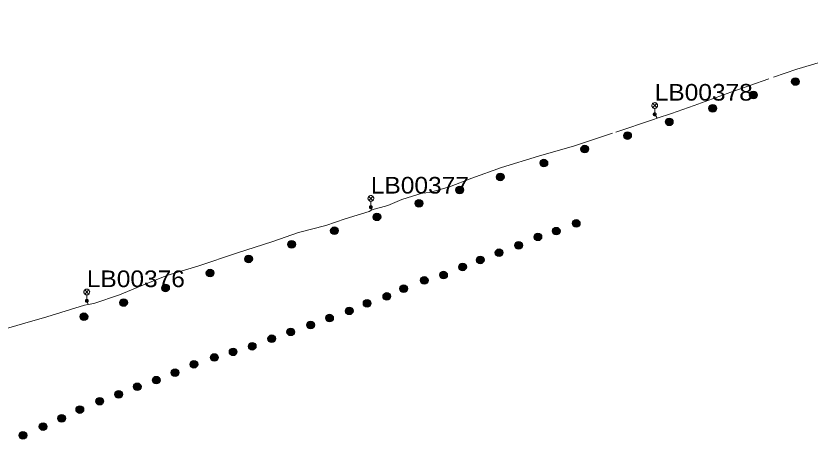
# Model space of a CAD drawing. Extents: x -688049 to -687261, y -973611 to -973038.
# Drawn here: x -687554.6 to -687451.2, y -973399.2 to -973344 of the extents above; entities that cross this region are included whole.
import ezdxf

# ---------------------------------------------------------------- set-up
doc = ezdxf.new("R2010")
doc.units = 0
doc.header["$LTSCALE"] = 0.87
doc.linetypes.add('LONG_DASH_SHORT_DASH', pattern=[9.9, 6, -1.2, 1.5, -1.2])
doc.layers.add('1', color=7, linetype='Continuous', lineweight=13)

msp = doc.modelspace()

# ---------------------------------------------------------------- hatches: boundary and pattern name
at = {"layer": '1'}
for points in [[(-687452.951, -973353.016, 1), (-687453.25, -973352.072, 1)], [(-687458.431, -973354.77, 1), (-687458.73, -973353.826, 1)], [(-687463.713, -973356.513, 1), (-687464.012, -973355.569, 1)], [(-687469.389, -973358.272, 1), (-687469.688, -973357.328, 1)], [(-687474.817, -973360.072, 1), (-687475.116, -973359.127, 1)], [(-687480.382, -973361.824, 1), (-687480.681, -973360.88, 1)], [(-687485.713, -973363.649, 1), (-687486.011, -973362.705, 1)], [(-687491.387, -973365.457, 1), (-687491.686, -973364.513, 1)], [(-687496.677, -973367.176, 1), (-687496.976, -973366.232, 1)], [(-687501.974, -973368.905, 1), (-687502.272, -973367.961, 1)], [(-687507.452, -973370.664, 1), (-687507.751, -973369.72, 1)], [(-687481.5, -973371.517, 1), (-687481.799, -973370.572, 1)], [(-687512.982, -973372.477, 1), (-687513.281, -973371.533, 1)], [(-687484.095, -973372.525, 1), (-687484.394, -973371.581, 1)], [(-687486.493, -973373.271, 1), (-687486.792, -973372.327, 1)], [(-687518.571, -973374.246, 1), (-687518.87, -973373.302, 1)], [(-687489.003, -973374.378, 1), (-687489.302, -973373.434, 1)], [(-687524.158, -973376.155, 1), (-687524.457, -973375.211, 1)], [(-687491.537, -973375.34, 1), (-687491.836, -973374.396, 1)], [(-687496.293, -973377.192, 1), (-687496.592, -973376.248, 1)], [(-687494, -973376.278, 1), (-687494.299, -973375.334, 1)], [(-687529.175, -973377.989, 1), (-687529.474, -973377.045, 1)], [(-687501.29, -973378.948, 1), (-687501.589, -973378.004, 1)], [(-687498.779, -973378.251, 1), (-687499.078, -973377.307, 1)], [(-687534.984, -973379.929, 1), (-687535.282, -973378.984, 1)], [(-687503.969, -973380.031, 1), (-687504.268, -973379.087, 1)], [(-687506.163, -973381.039, 1), (-687506.462, -973380.094, 1)], [(-687540.439, -973381.836, 1), (-687540.738, -973380.892, 1)], [(-687508.725, -973381.939, 1), (-687509.024, -973380.995, 1)], [(-687511.053, -973382.922, 1), (-687511.352, -973381.978, 1)], [(-687545.616, -973383.691, 1), (-687545.915, -973382.747, 1)], [(-687513.625, -973383.867, 1), (-687513.924, -973382.923, 1)], [(-687516.092, -973384.765, 1), (-687516.39, -973383.821, 1)], [(-687518.679, -973385.662, 1), (-687518.978, -973384.717, 1)], [(-687521.141, -973386.555, 1), (-687521.44, -973385.611, 1)], [(-687526.174, -973388.267, 1), (-687526.473, -973387.323, 1)], [(-687523.698, -973387.538, 1), (-687523.996, -973386.594, 1)], [(-687528.627, -973389.002, 1), (-687528.925, -973388.058, 1)], [(-687531.283, -973389.89, 1), (-687531.582, -973388.946, 1)], [(-687533.745, -973390.997, 1), (-687534.044, -973390.053, 1)], [(-687536.183, -973391.959, 1), (-687536.482, -973391.015, 1)], [(-687538.669, -973392.825, 1), (-687538.968, -973391.881, 1)], [(-687543.546, -973394.702, 1), (-687543.845, -973393.757, 1)], [(-687541.083, -973393.812, 1), (-687541.382, -973392.867, 1)], [(-687546.141, -973395.793, 1), (-687546.44, -973394.848, 1)], [(-687548.507, -973396.95, 1), (-687548.806, -973396.006, 1)], [(-687550.927, -973398.011, 1), (-687551.226, -973397.066, 1)], [(-687553.553, -973399.155, 1), (-687553.852, -973398.21, 1)]]:
    msp.add_hatch(color=256, dxfattribs=at).paths.add_polyline_path(points)

# ---------------------------------------------------------------- linework, layer by layer
for p, q in [((-687471.685, -973355.405), (-687471.155, -973355.935)), ((-687471.685, -973355.935), (-687471.155, -973355.405)), ((-687471.42, -973356.82), (-687471.42, -973356.045)), ((-687508.655, -973367.525), (-687508.125, -973368.055)), ((-687508.655, -973368.055), (-687508.125, -973367.525)), ((-687508.39, -973368.94), (-687508.39, -973368.165)), ((-687545.645, -973379.725), (-687545.115, -973380.255)), ((-687545.645, -973380.255), (-687545.115, -973379.725)), ((-687545.38, -973381.14), (-687545.38, -973380.365))]:
    msp.add_line(p, q, dxfattribs=at)
at = {"layer": '1', "linetype": 'LONG_DASH_SHORT_DASH'}
for p, q in [((-687471.1, -973357.3), (-687471.42, -973356.82)), ((-687508.25, -973369.29), (-687508.39, -973368.94)), ((-687545.21, -973381.61), (-687545.38, -973381.14))]:
    msp.add_line(p, q, dxfattribs=at)
for points in [[(-687471.1, -973357.3), (-687469.23, -973356.72), (-687466.28, -973355.69), (-687461.51, -973353.91), (-687455.96, -973351.99), (-687452.92, -973350.95), (-687449.84, -973350.04), (-687445.86, -973348.71), (-687442.97, -973347.78), (-687439.3, -973347.01), (-687435.78, -973345.76), (-687433.52, -973344.93), (-687431.83, -973344.36), (-687431.72, -973343.98)], [(-687508.25, -973369.29), (-687506.19, -973368.71), (-687504.36, -973367.92), (-687501.72, -973367.12), (-687500.76, -973367.03), (-687498.15, -973366.29), (-687495.25, -973365.16), (-687491.39, -973363.77), (-687486.58, -973362.27), (-687481.87, -973360.93), (-687476.48, -973359.14), (-687471.58, -973357.5), (-687471.1, -973357.3)], [(-687545.21, -973381.61), (-687544.47, -973381.51), (-687541.13, -973380.37), (-687538.32, -973379.2), (-687534.96, -973377.86), (-687530.79, -973376.56), (-687525.89, -973374.94), (-687521.16, -973373.42), (-687517.8, -973372.25), (-687514.26, -973371.3), (-687511.73, -973370.43), (-687508.63, -973369.51), (-687508.25, -973369.29)], [(-687556.57, -973384.95), (-687553.44, -973384.04), (-687550.57, -973383.25), (-687545.68, -973381.7), (-687545.21, -973381.61)]]:
    msp.add_lwpolyline(points, dxfattribs=at)
at = {"layer": '1'}
for points in [[(-687471.045, -973355.67), (-687471.051, -973355.605), (-687471.068, -973355.542), (-687471.095, -973355.482), (-687471.133, -973355.429), (-687471.179, -973355.383), (-687471.232, -973355.345), (-687471.292, -973355.318), (-687471.355, -973355.301), (-687471.42, -973355.295), (-687471.485, -973355.301), (-687471.548, -973355.318), (-687471.608, -973355.345), (-687471.661, -973355.383), (-687471.707, -973355.429), (-687471.745, -973355.482), (-687471.772, -973355.542), (-687471.789, -973355.605), (-687471.795, -973355.67), (-687471.789, -973355.735), (-687471.772, -973355.798), (-687471.745, -973355.857), (-687471.707, -973355.911), (-687471.661, -973355.957), (-687471.608, -973355.995), (-687471.548, -973356.022), (-687471.485, -973356.039), (-687471.42, -973356.045), (-687471.355, -973356.039), (-687471.292, -973356.022), (-687471.232, -973355.995), (-687471.179, -973355.957), (-687471.133, -973355.911), (-687471.095, -973355.857), (-687471.068, -973355.798), (-687471.051, -973355.735)], [(-687471.23, -973356.82), (-687471.233, -973356.787), (-687471.241, -973356.755), (-687471.255, -973356.725), (-687471.274, -973356.698), (-687471.298, -973356.674), (-687471.325, -973356.655), (-687471.355, -973356.641), (-687471.387, -973356.633), (-687471.42, -973356.63), (-687471.453, -973356.633), (-687471.485, -973356.641), (-687471.515, -973356.655), (-687471.542, -973356.674), (-687471.566, -973356.698), (-687471.585, -973356.725), (-687471.599, -973356.755), (-687471.607, -973356.787), (-687471.61, -973356.82), (-687471.607, -973356.853), (-687471.599, -973356.885), (-687471.585, -973356.915), (-687471.566, -973356.942), (-687471.542, -973356.966), (-687471.515, -973356.985), (-687471.485, -973356.999), (-687471.453, -973357.007), (-687471.42, -973357.01), (-687471.387, -973357.007), (-687471.355, -973356.999), (-687471.325, -973356.985), (-687471.298, -973356.966), (-687471.274, -973356.942), (-687471.255, -973356.915), (-687471.241, -973356.885), (-687471.233, -973356.853)], [(-687471.37, -973356.82), (-687471.371, -973356.811), (-687471.373, -973356.803), (-687471.377, -973356.795), (-687471.382, -973356.788), (-687471.388, -973356.782), (-687471.395, -973356.777), (-687471.403, -973356.773), (-687471.411, -973356.771), (-687471.42, -973356.77), (-687471.429, -973356.771), (-687471.437, -973356.773), (-687471.445, -973356.777), (-687471.452, -973356.782), (-687471.458, -973356.788), (-687471.463, -973356.795), (-687471.467, -973356.803), (-687471.469, -973356.811), (-687471.47, -973356.82), (-687471.469, -973356.829), (-687471.467, -973356.837), (-687471.463, -973356.845), (-687471.458, -973356.852), (-687471.452, -973356.858), (-687471.445, -973356.863), (-687471.437, -973356.867), (-687471.429, -973356.869), (-687471.42, -973356.87), (-687471.411, -973356.869), (-687471.403, -973356.867), (-687471.395, -973356.863), (-687471.388, -973356.858), (-687471.382, -973356.852), (-687471.377, -973356.845), (-687471.373, -973356.837), (-687471.371, -973356.829)], [(-687508.015, -973367.79), (-687508.021, -973367.725), (-687508.038, -973367.662), (-687508.065, -973367.602), (-687508.103, -973367.549), (-687508.149, -973367.503), (-687508.202, -973367.465), (-687508.262, -973367.438), (-687508.325, -973367.421), (-687508.39, -973367.415), (-687508.455, -973367.421), (-687508.518, -973367.438), (-687508.578, -973367.465), (-687508.631, -973367.503), (-687508.677, -973367.549), (-687508.715, -973367.602), (-687508.742, -973367.662), (-687508.759, -973367.725), (-687508.765, -973367.79), (-687508.759, -973367.855), (-687508.742, -973367.918), (-687508.715, -973367.977), (-687508.677, -973368.031), (-687508.631, -973368.077), (-687508.578, -973368.115), (-687508.518, -973368.142), (-687508.455, -973368.159), (-687508.39, -973368.165), (-687508.325, -973368.159), (-687508.262, -973368.142), (-687508.202, -973368.115), (-687508.149, -973368.077), (-687508.103, -973368.031), (-687508.065, -973367.977), (-687508.038, -973367.918), (-687508.021, -973367.855)], [(-687508.2, -973368.94), (-687508.203, -973368.907), (-687508.211, -973368.875), (-687508.225, -973368.845), (-687508.244, -973368.818), (-687508.268, -973368.794), (-687508.295, -973368.775), (-687508.325, -973368.761), (-687508.357, -973368.753), (-687508.39, -973368.75), (-687508.423, -973368.753), (-687508.455, -973368.761), (-687508.485, -973368.775), (-687508.512, -973368.794), (-687508.536, -973368.818), (-687508.555, -973368.845), (-687508.569, -973368.875), (-687508.577, -973368.907), (-687508.58, -973368.94), (-687508.577, -973368.973), (-687508.569, -973369.005), (-687508.555, -973369.035), (-687508.536, -973369.062), (-687508.512, -973369.086), (-687508.485, -973369.105), (-687508.455, -973369.119), (-687508.423, -973369.127), (-687508.39, -973369.13), (-687508.357, -973369.127), (-687508.325, -973369.119), (-687508.295, -973369.105), (-687508.268, -973369.086), (-687508.244, -973369.062), (-687508.225, -973369.035), (-687508.211, -973369.005), (-687508.203, -973368.973)], [(-687508.34, -973368.94), (-687508.341, -973368.931), (-687508.343, -973368.923), (-687508.347, -973368.915), (-687508.352, -973368.908), (-687508.358, -973368.902), (-687508.365, -973368.897), (-687508.373, -973368.893), (-687508.381, -973368.891), (-687508.39, -973368.89), (-687508.399, -973368.891), (-687508.407, -973368.893), (-687508.415, -973368.897), (-687508.422, -973368.902), (-687508.428, -973368.908), (-687508.433, -973368.915), (-687508.437, -973368.923), (-687508.439, -973368.931), (-687508.44, -973368.94), (-687508.439, -973368.949), (-687508.437, -973368.957), (-687508.433, -973368.965), (-687508.428, -973368.972), (-687508.422, -973368.978), (-687508.415, -973368.983), (-687508.407, -973368.987), (-687508.399, -973368.989), (-687508.39, -973368.99), (-687508.381, -973368.989), (-687508.373, -973368.987), (-687508.365, -973368.983), (-687508.358, -973368.978), (-687508.352, -973368.972), (-687508.347, -973368.965), (-687508.343, -973368.957), (-687508.341, -973368.949)], [(-687545.005, -973379.99), (-687545.011, -973379.925), (-687545.028, -973379.862), (-687545.055, -973379.802), (-687545.093, -973379.749), (-687545.139, -973379.703), (-687545.192, -973379.665), (-687545.252, -973379.638), (-687545.315, -973379.621), (-687545.38, -973379.615), (-687545.445, -973379.621), (-687545.508, -973379.638), (-687545.568, -973379.665), (-687545.621, -973379.703), (-687545.667, -973379.749), (-687545.705, -973379.802), (-687545.732, -973379.862), (-687545.749, -973379.925), (-687545.755, -973379.99), (-687545.749, -973380.055), (-687545.732, -973380.118), (-687545.705, -973380.178), (-687545.667, -973380.231), (-687545.621, -973380.277), (-687545.568, -973380.315), (-687545.508, -973380.342), (-687545.445, -973380.359), (-687545.38, -973380.365), (-687545.315, -973380.359), (-687545.252, -973380.342), (-687545.192, -973380.315), (-687545.139, -973380.277), (-687545.093, -973380.231), (-687545.055, -973380.178), (-687545.028, -973380.118), (-687545.011, -973380.055)], [(-687545.19, -973381.14), (-687545.193, -973381.107), (-687545.201, -973381.075), (-687545.215, -973381.045), (-687545.234, -973381.018), (-687545.258, -973380.994), (-687545.285, -973380.975), (-687545.315, -973380.961), (-687545.347, -973380.953), (-687545.38, -973380.95), (-687545.413, -973380.953), (-687545.445, -973380.961), (-687545.475, -973380.975), (-687545.502, -973380.994), (-687545.526, -973381.018), (-687545.545, -973381.045), (-687545.559, -973381.075), (-687545.567, -973381.107), (-687545.57, -973381.14), (-687545.567, -973381.173), (-687545.559, -973381.205), (-687545.545, -973381.235), (-687545.526, -973381.262), (-687545.502, -973381.286), (-687545.475, -973381.305), (-687545.445, -973381.319), (-687545.413, -973381.327), (-687545.38, -973381.33), (-687545.347, -973381.327), (-687545.315, -973381.319), (-687545.285, -973381.305), (-687545.258, -973381.286), (-687545.234, -973381.262), (-687545.215, -973381.235), (-687545.201, -973381.205), (-687545.193, -973381.173)], [(-687545.33, -973381.14), (-687545.331, -973381.131), (-687545.333, -973381.123), (-687545.337, -973381.115), (-687545.342, -973381.108), (-687545.348, -973381.102), (-687545.355, -973381.097), (-687545.363, -973381.093), (-687545.371, -973381.091), (-687545.38, -973381.09), (-687545.389, -973381.091), (-687545.397, -973381.093), (-687545.405, -973381.097), (-687545.412, -973381.102), (-687545.418, -973381.108), (-687545.423, -973381.115), (-687545.427, -973381.123), (-687545.429, -973381.131), (-687545.43, -973381.14), (-687545.429, -973381.149), (-687545.427, -973381.157), (-687545.423, -973381.165), (-687545.418, -973381.172), (-687545.412, -973381.178), (-687545.405, -973381.183), (-687545.397, -973381.187), (-687545.389, -973381.189), (-687545.38, -973381.19), (-687545.371, -973381.189), (-687545.363, -973381.187), (-687545.355, -973381.183), (-687545.348, -973381.178), (-687545.342, -973381.172), (-687545.337, -973381.165), (-687545.333, -973381.157), (-687545.331, -973381.149)]]:
    msp.add_lwpolyline(points, close=True, dxfattribs=at)
at = {"layer": '1', "lineweight": 25}
for centre in [(-687453.1, -973352.544), (-687458.581, -973354.298), (-687463.863, -973356.041), (-687469.538, -973357.8), (-687474.966, -973359.6), (-687480.531, -973361.352), (-687485.862, -973363.177), (-687491.537, -973364.985), (-687496.826, -973366.704), (-687502.123, -973368.433), (-687507.602, -973370.192), (-687481.649, -973371.044), (-687513.132, -973372.005), (-687484.245, -973372.053), (-687486.642, -973372.799), (-687518.72, -973373.774), (-687489.152, -973373.906), (-687524.307, -973375.683), (-687491.687, -973374.868), (-687496.443, -973376.72), (-687494.149, -973375.806), (-687529.325, -973377.517), (-687501.439, -973378.476), (-687498.929, -973377.779), (-687535.133, -973379.457), (-687504.118, -973379.559), (-687506.312, -973380.566), (-687540.588, -973381.364), (-687508.875, -973381.467), (-687511.202, -973382.45), (-687545.765, -973383.219), (-687513.774, -973383.395), (-687516.241, -973384.293), (-687518.829, -973385.189), (-687521.291, -973386.083), (-687526.323, -973387.795), (-687523.847, -973387.066), (-687528.776, -973388.53), (-687531.432, -973389.418), (-687533.895, -973390.525), (-687536.333, -973391.487), (-687538.819, -973392.353), (-687543.695, -973394.229), (-687541.233, -973393.34), (-687546.291, -973395.321), (-687548.656, -973396.478), (-687551.077, -973397.539), (-687553.702, -973398.682)]:
    msp.add_circle(centre, 0.495, dxfattribs=at)

# ---------------------------------------------------------------- texts
at = {"layer": '1', "width": 1.1}
for s, p in [('LB00378', (-687471.42, -973355.032)), ('LB00377', (-687508.39, -973367.152)), ('LB00376', (-687545.38, -973379.352))]:
    msp.add_text(s, height=2.168, dxfattribs=at).set_placement(p)

doc.saveas('drawing.dxf')
